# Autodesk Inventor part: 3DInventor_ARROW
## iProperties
Created: 2006-11
Part Number: 3DInventor_ARROW
Document SubType Name: Modeling
Designer: conardl1
Density: 1 g/cm^3
DESCRIPTION: Arrow Control Pad
MODELED_BY: L Conard
Author: conardl1
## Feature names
1. Base1
